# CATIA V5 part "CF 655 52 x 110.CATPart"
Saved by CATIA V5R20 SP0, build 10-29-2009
Part number: CF 655 52 x 110
Definition: NONE
Nomenclature: CF 655 52 x 110
Source: Unknown
Description: CF 655 52 x 110
Bounding box of the stored display mesh (mm): x -75 to 35, y -39.5 to 39.5, z -39.5 to 39.5
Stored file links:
  C:\Users\Utente\Desktop\IO LAVORO\3D X SITO CF\X SITO\CF 655\CF 655 52 x 110.CATPart
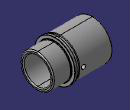
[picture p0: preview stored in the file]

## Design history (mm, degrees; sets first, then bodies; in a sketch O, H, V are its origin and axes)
Body1 "CF 655 52 x 110" (main body)
  Solid1: solid without history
